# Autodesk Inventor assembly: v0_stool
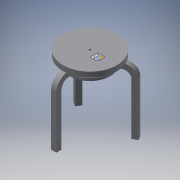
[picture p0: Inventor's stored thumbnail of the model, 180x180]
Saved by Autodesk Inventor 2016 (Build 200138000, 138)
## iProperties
Created: 2015-07
Part Number: v0_stool
Document SubType Name: Assembly
Designer: t_patrw
Author: t_patrw
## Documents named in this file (5)
- C:\Users\t_patrw\Documents\Inventor\Stoolv0\v0_stool.iam
- C:\Users\t_patrw\Documents\Inventor\Stoolv0\v0_stool_leg.ipt
- C:\Users\t_patrw\Documents\Inventor\Stoolv0\v0_stool_press.ipt
- C:\Users\t_patrw\Documents\Inventor\Stoolv0\v0_stool_seatbottom.ipt
- C:\Users\t_patrw\Documents\Inventor\Stoolv0\v0_stool_seattop.ipt
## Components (9 placed, 4 different names)
1. v0_stool_leg:1 — Rigid:2, Mate:9
2. v0_stool_press:1 — Mate:4, Mate:5
3. v0_stool_seatbottom:1 — Rotational:1, Mate:4, Rigid:4, Mate:7, Mate:9, Mate:10, Mate:11
4. v0_stool_seattop:1 — Rotational:1, Mate:6, Mate:8
5. v0_stool_leg:2 — Rigid:1, Mate:6, Mate:7, Mate:11
6. v0_stool_leg:3 — Rigid:1
7. v0_stool_leg:4 — Rigid:2, Mate:8, Mate:10
8. v0_stool_leg:5 — Rigid:3
9. v0_stool_leg:6 — Rigid:3, Rigid:4, Mate:5
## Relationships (13: Mate 8, WeldJoint 4, RevoluteJoint 1)
- Rotational:1 [RevoluteJoint]: v0_stool_seatbottom:1 ↔ v0_stool_seattop:1
- Mate:4: v0_stool_press:1 ↔ v0_stool_seatbottom:1
- Rigid:1 [WeldJoint]: v0_stool_leg:2 ↔ v0_stool_leg:3
- Rigid:2 [WeldJoint]: v0_stool_leg:1 ↔ v0_stool_leg:4
- Rigid:3 [WeldJoint]: v0_stool_leg:5 ↔ v0_stool_leg:6
- Rigid:4 [WeldJoint]: v0_stool_seatbottom:1 ↔ v0_stool_leg:6
- Mate:5: v0_stool_press:1 ↔ v0_stool_leg:6
- Mate:6: v0_stool_seattop:1 ↔ v0_stool_leg:2
- Mate:7: v0_stool_seatbottom:1 ↔ v0_stool_leg:2
- Mate:8: v0_stool_seattop:1 ↔ v0_stool_leg:4
- Mate:9: v0_stool_leg:1 ↔ v0_stool_seatbottom:1
- Mate:10: v0_stool_seatbottom:1 ↔ v0_stool_leg:4
- Mate:11: v0_stool_seatbottom:1 ↔ v0_stool_leg:2
